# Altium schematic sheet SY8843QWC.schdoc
size 127 x 101 mm
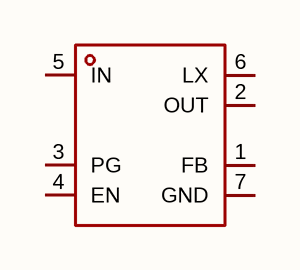
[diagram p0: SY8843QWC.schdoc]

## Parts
U?  sy8843qwc  [QFN-7_L1.5-W1.5-P0.45-BL_SILERGY_SY8842QWC]  (value not drawn)

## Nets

Not connected (* = marked no-connect by the designer): U? 1(FB) 2(OUT) 3(PG) 4(EN) 5(IN) 6(LX) 7(GND)

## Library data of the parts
U? = sy8843qwc: 功能类型:降压型;工作电压:2.7V~5.5V;输出电压:-;输出电流:3A;输出类型:可调;; Manufacturer: Silergy(矽力杰); AddInBom: yes; ModelId: f3bb5fc7e8804ea88e1edd7067b238ed; ModelTransform: 59.055,59.055,0,0,0,0,3.936,3.228,0; Function: 降压型; Output Current: 3A; Frequency - Switching: 1.5MHz; Synchronous Rectifier: 是; Number of Outputs: 1; Topology: 降压式; Quiescent Current: 65uA; Switch tube (built-in/external): 内置; Output Type: 可调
